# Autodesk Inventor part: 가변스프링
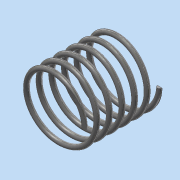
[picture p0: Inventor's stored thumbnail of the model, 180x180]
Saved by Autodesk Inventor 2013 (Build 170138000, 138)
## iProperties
Created: 2018-02
Part Number: 가변스프링
Material: 스테인리스강
Document SubType Name: Modeling
Designer: dgall
Density: 8.08 g/cm^3
Mass: 42.4869 g
Surface Area: 70.8603 cm^2
Volume: 5.25828 cm^3
Author: dgall
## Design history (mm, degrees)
sketch "스케치1"
  geometry: L1 (0, 0)-(20, 0); L2 (0, 0)-(0, 47.25); L3 (0, 47.25)-(20, 47.25); C1 r 1.5 at (20, 0)
  constraints: 6 end point, 2 perpendicular, 1 centre point, 1 coincident, 1 horizontal, 1 vertical alignment
  dimensions: "d0" = 47.25 distance of L1.start L2.end (derived); "d1" = 40 diameter of L1.end L2; "d2" = 3 diameter of C1
feature "코일1" sketch "스케치1" pitch "d3" = 10; turns "d5" = 6; dims "d4" = 47.25 (= d0), "d6" = 0, angle "d7" = 90 deg, angle "d8" = 90 deg, "d9" = 0, "d10" = 0
node "작업 평면1"
feature "분할1"
feature "분할3"
node "솔리드1"
